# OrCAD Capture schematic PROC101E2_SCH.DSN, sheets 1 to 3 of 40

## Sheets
1 04. BLOCK DIAGRAM_XDS110: title: BLOCK DIAGRAM_XDS110; rev: E2
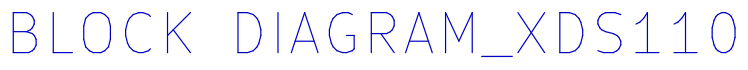
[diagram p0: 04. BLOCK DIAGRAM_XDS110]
2 16. CPSW RGMII_1 ETHERNET PHY: size C; title: CPSW RGMII_1 ETHERNET PHY
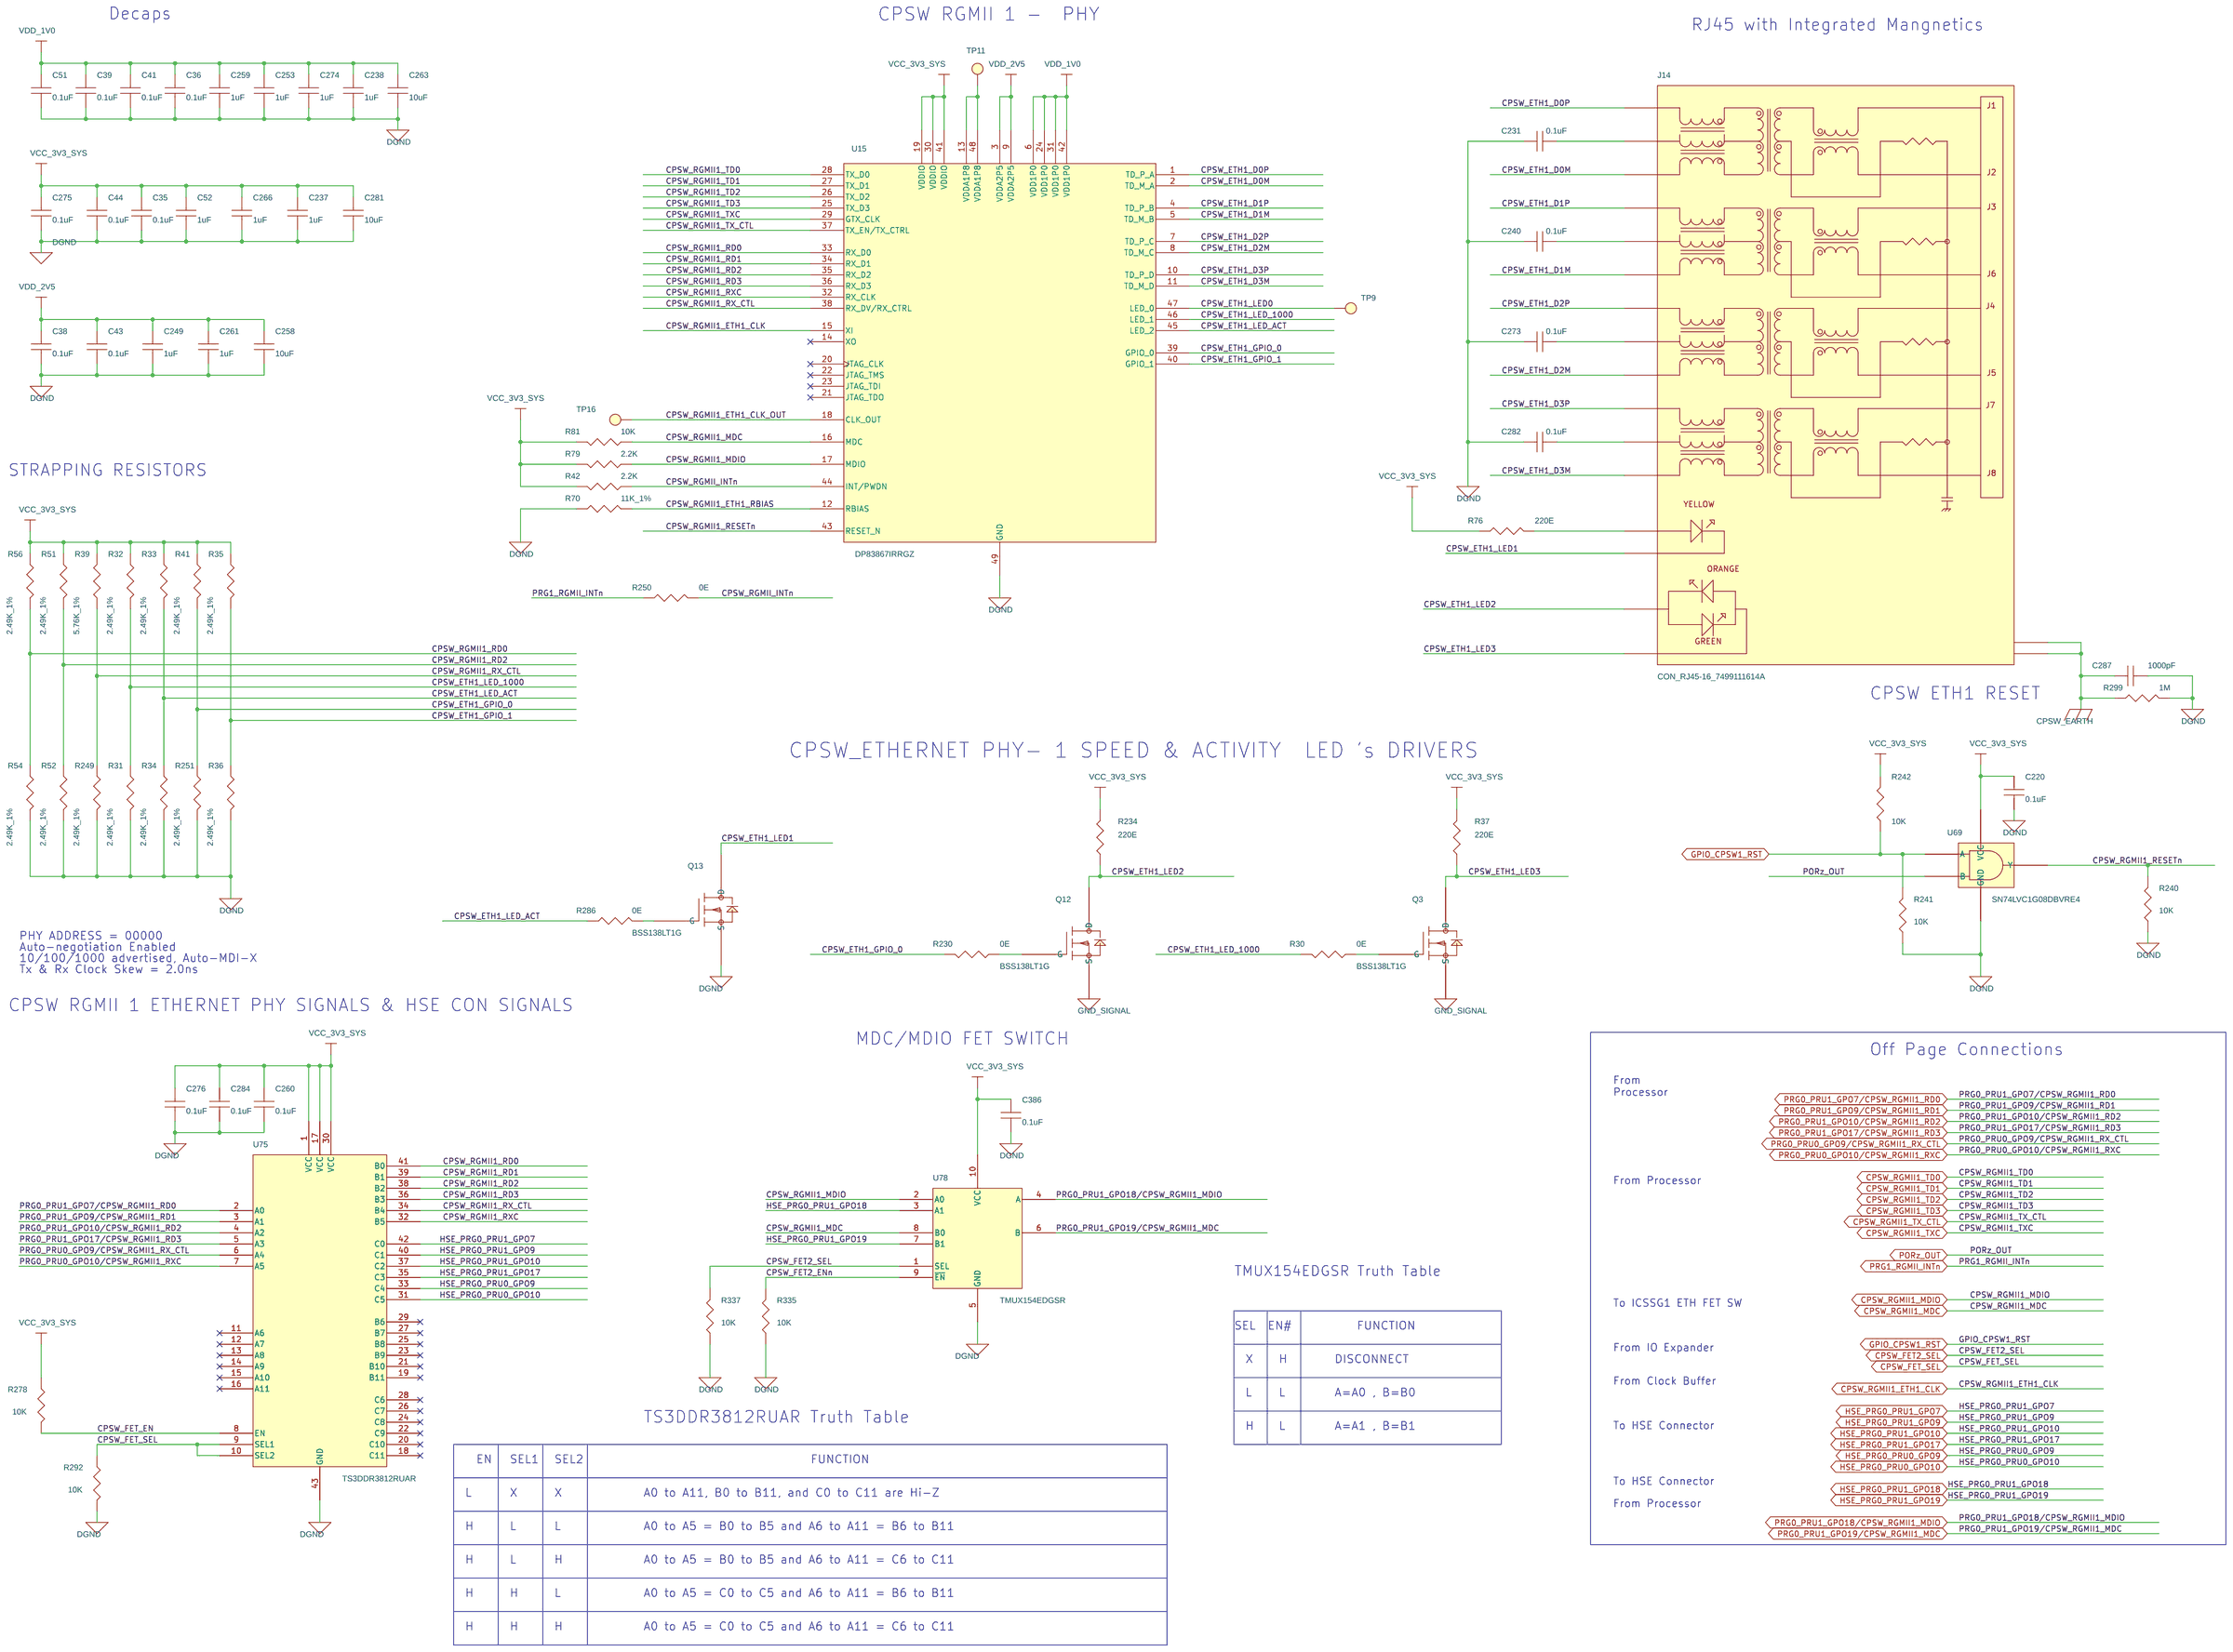
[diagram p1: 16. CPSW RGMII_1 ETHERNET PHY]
3 10.SOC POWER CAPS: size C; title: SOC POWER CAPS
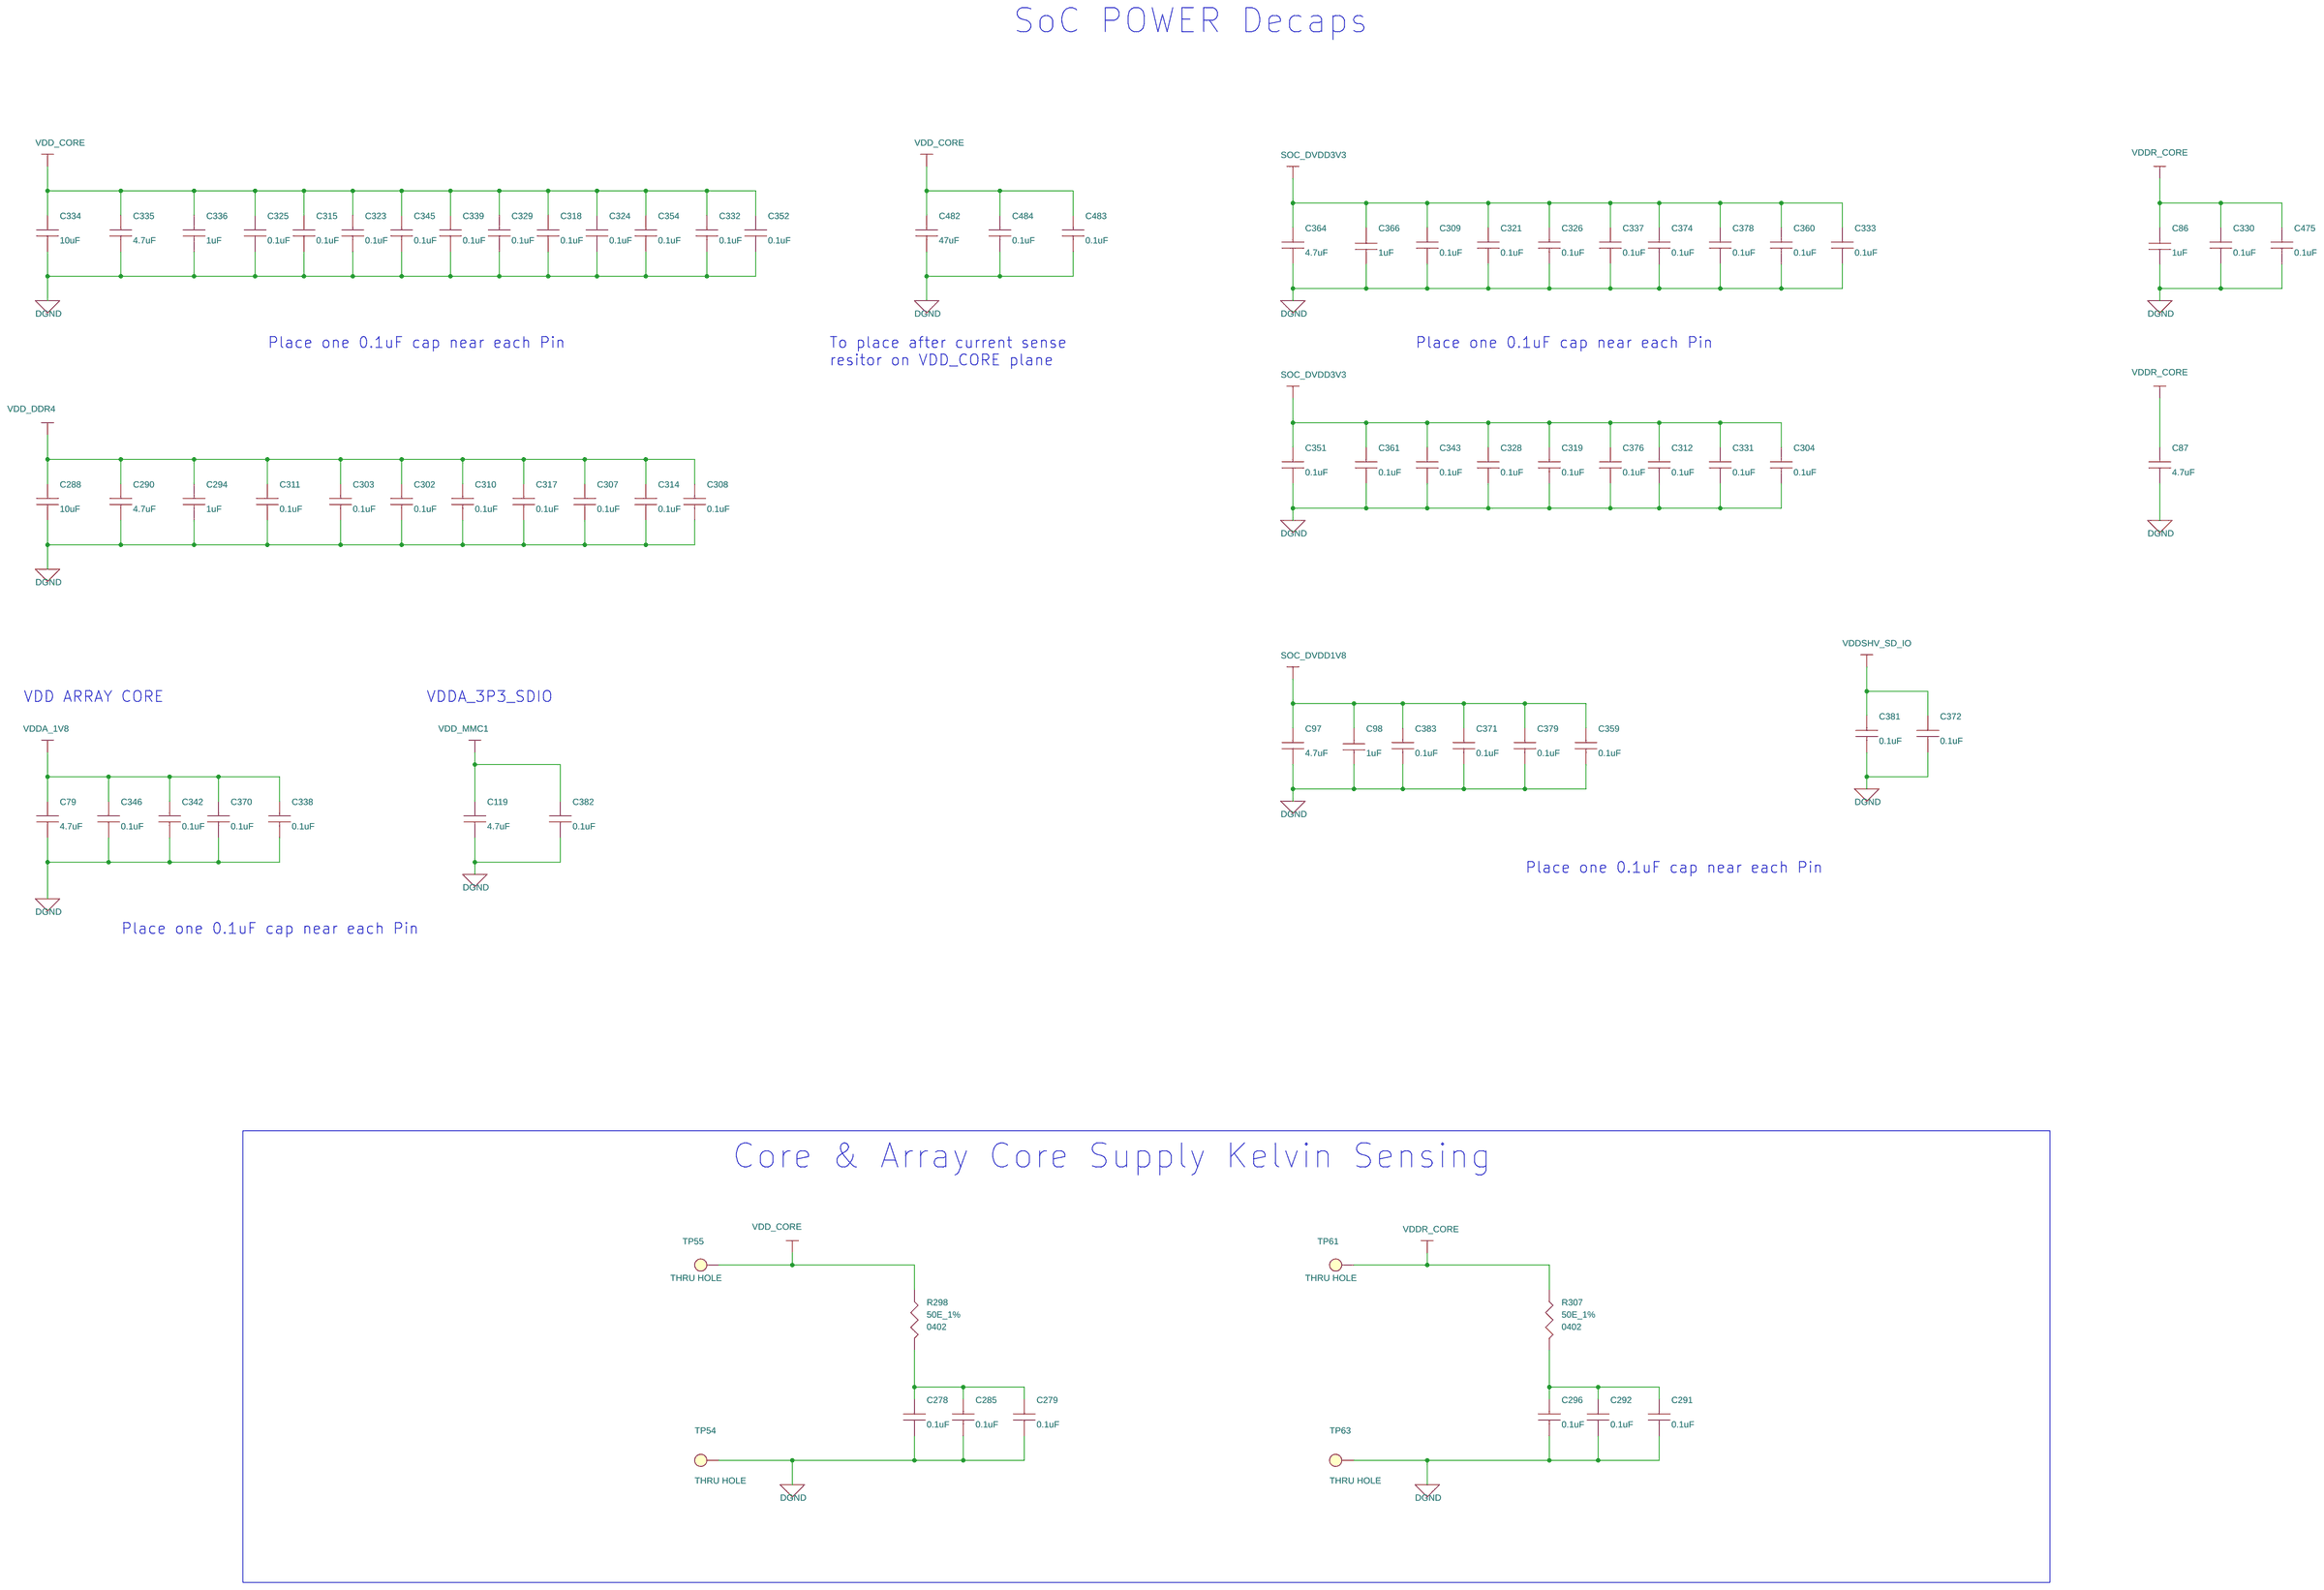
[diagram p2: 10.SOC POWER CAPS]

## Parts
sheet 10.SOC POWER CAPS
C79  4.7uF  [CAP0402_0-75]
C86  1uF  [CAP0402_0-75]
C87  4.7uF  [CAP0402_0-75]
C97  4.7uF  [CAP0402_0-75]
C98  1uF  [CAP0402_0-75]
C119  4.7uF  [CAP0402_0-75]
C278  0.1uF  [CAP0402_0-75]
C279  0.1uF  [CAP0402_0-75]
C285  0.1uF  [CAP0402_0-75]
C288  10uF  [CAP0402_0-75]
C290  4.7uF  [CAP0402_0-75]
C291  0.1uF  [CAP0402_0-75]
C292  0.1uF  [CAP0402_0-75]
C294  1uF  [CAP0402_0-75]
C296  0.1uF  [CAP0402_0-75]
C302  0.1uF  [CAP0201_0-5]
C303  0.1uF  [CAP0201_0-5]
C304  0.1uF  [CAP0201_0-5]
C307  0.1uF  [CAP0201_0-5]
C308  0.1uF  [CAP0201_0-5]
C309  0.1uF  [CAP0201_0-5]
C310  0.1uF  [CAP0201_0-5]
C311  0.1uF  [CAP0201_0-5]
C312  0.1uF  [CAP0201_0-5]
C314  0.1uF  [CAP0201_0-5]
C315  0.1uF  [CAP0201_0-5]
C317  0.1uF  [CAP0201_0-5]
C318  0.1uF  [CAP0201_0-5]
C319  0.1uF  [CAP0201_0-5]
C321  0.1uF  [CAP0201_0-5]
C323  0.1uF  [CAP0201_0-5]
C324  0.1uF  [CAP0201_0-5]
C325  0.1uF  [CAP0201_0-5]
C326  0.1uF  [CAP0201_0-5]
C328  0.1uF  [CAP0201_0-5]
C329  0.1uF  [CAP0201_0-5]
C330  0.1uF  [CAP0201_0-5]
C331  0.1uF  [CAP0201_0-5]
C332  0.1uF  [CAP0201_0-5]
C333  0.1uF  [CAP0201_0-5]
C334  10uF  [CAP0402_0-75]
C335  4.7uF  [CAP0402_0-75]
C336  1uF  [CAP0402_0-75]
C337  0.1uF  [CAP0201_0-5]
C338  0.1uF  [CAP0201_0-5]
C339  0.1uF  [CAP0201_0-5]
C342  0.1uF  [CAP0201_0-5]
C343  0.1uF  [CAP0201_0-5]
C345  0.1uF  [CAP0201_0-5]
C346  0.1uF  [CAP0201_0-5]
C351  0.1uF  [CAP0201_0-5]
C352  0.1uF  [CAP0201_0-5]
C354  0.1uF  [CAP0201_0-5]
C359  0.1uF  [CAP0201_0-5]
C360  0.1uF  [CAP0201_0-5]
C361  0.1uF  [CAP0201_0-5]
C364  4.7uF  [CAP0402_0-75]
C366  1uF  [CAP0402_0-75]
C370  0.1uF  [CAP0201_0-5]
C371  0.1uF  [CAP0201_0-5]
C372  0.1uF  [CAP0201_0-5]
C374  0.1uF  [CAP0201_0-5]
C376  0.1uF  [CAP0201_0-5]
C378  0.1uF  [CAP0201_0-5]
C379  0.1uF  [CAP0201_0-5]
C381  0.1uF  [CAP0201_0-5]
C382  0.1uF  [CAP0201_0-5]
C383  0.1uF  [CAP0201_0-5]
C475  0.1uF  [CAP0201_0-5]
C482  47uF  [CAP1206_2]
C483  0.1uF  [CAP0201_0-5]
C484  0.1uF  [CAP0201_0-5]
R298  50E_1%  [RES0402_0-75]
R307  50E_1%  [RES0402_0-75]
TP54  THRU HOLE  [TP_40X65]
TP55  THRU HOLE  [TP_40X65]
TP61  THRU HOLE  [TP_40X65]
TP63  THRU HOLE  [TP_40X65]
sheet 16. CPSW RGMII_1 ETHERNET PHY
C35  0.1uF  [CAP0402_0-75]
C36  0.1uF  [CAP0402_0-75]
C38  0.1uF  [CAP0402_0-75]
C39  0.1uF  [CAP0402_0-75]
C41  0.1uF  [CAP0402_0-75]
C43  0.1uF  [CAP0402_0-75]
C44  0.1uF  [CAP0402_0-75]
C51  0.1uF  [CAP0402_0-75]
C52  1uF  [CAP0402_0-75]
C220  0.1uF  [CAP0402_0-75]
C231  0.1uF  [CAP0201_0-5]
C237  1uF  [CAP0402_0-75]
C238  1uF  [CAP0402_0-75]
C240  0.1uF  [CAP0201_0-5]
C249  1uF  [CAP0402_0-75]
C253  1uF  [CAP0402_0-75]
C258  10uF  [CAP0402_0-75]
C259  1uF  [CAP0402_0-75]
C260  0.1uF  [CAP0402_0-75]
C261  1uF  [CAP0402_0-75]
C263  10uF  [CAP0402_0-75]
C266  1uF  [CAP0402_0-75]
C273  0.1uF  [CAP0201_0-5]
C274  1uF  [CAP0402_0-75]
C275  0.1uF  [CAP0402_0-75]
C276  0.1uF  [CAP0402_0-75]
C281  10uF  [CAP0402_0-75]
C282  0.1uF  [CAP0201_0-5]
C284  0.1uF  [CAP0402_0-75]
C287  1000pF  [CAP1206_1-75]
C386  0.1uF  [CAP0402_0-75]
J14  CON_RJ45-16_7499111614A  [CON_RJ45-16_7499111614A_S_R_T_15-8]
Q3  BSS138LT1G  [SOT23-123_1-2]
Q12  BSS138LT1G  [SOT23-123_1-2]
Q13  BSS138LT1G  [SOT23-123_1-2]
R30  0E  [RES0402_0-5]
R31  2.49K_1%  [RES0402_0-5]
R32  2.49K_1%  [RES0402_0-5]
R33  2.49K_1%  [RES0402_0-5]
R34  2.49K_1%  [RES0402_0-5]
R35  2.49K_1%  [RES0402_0-5]
R36  2.49K_1%  [RES0402_0-5]
R37  220E  [RES0402_0-5]
R39  5.76K_1%  [RES0402_0-5]
R41  2.49K_1%  [RES0402_0-5]
R42  2.2K  [RES0402_0-5]
R51  2.49K_1%  [RES0402_0-5]
R52  2.49K_1%  [RES0402_0-5]
R54  2.49K_1%  [RES0402_0-5]
R56  2.49K_1%  [RES0402_0-5]
R70  11K_1%  [RES0402_0-5]
R76  220E  [RES0402_0-5]
R79  2.2K  [RES0402_0-5]
R81  10K  [RES0402_0-5]
R230  0E  [RES0402_0-5]
R234  220E  [RES0402_0-5]
R240  10K  [RES0402_0-5]
R241  10K  [RES0402_0-5]
R242  10K  [RES0402_0-5]
R249  2.49K_1%  [RES0402_0-5]
R250  0E  [RES0402_0-5]
R251  2.49K_1%  [RES0402_0-5]
R278  10K  [RES0402_0-5]
R286  0E  [RES0402_0-5]
R292  10K  [RES0402_0-5]
R299  1M  [RES0603_0-75]
R335  10K  [RES0402_0-5]
R337  10K  [RES0402_0-5]
TP9  TP20_SMD  [TP20_SMD]
TP11  TP20_SMD  [TP20_SMD]
TP16  TP20_SMD  [TP20_SMD]
U15  DP83867IRRGZ  [QFN48_19-68_280X280_1]
U69  SN74LVC1G08DBVRE4  [SOT23-5]
U75  TS3DDR3812RUAR  [TQFN42_19-68_140X360_0-8]
U78  TMUX154EDGSR  [MSOP10_19-68_120X120_1-1]

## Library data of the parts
C79 C87 C97 C119 C290 C335 C364 = CAP: CAP CERAMIC 4.7uF 10V 20% X5R 0402; Chkd/date: MANIRAJA/230118; Crtd /date: MANIRAJA/230118; Custom_Duty: 15%; Customs_HS_Code: 85322990; Distributor_name: DIGIKEY; Distributor_part_number: 478-10791-1-ND; Footprint Path: Y:\MIS_DATABASE\Library\ALTIUM_TOOL\PCB_FOOTPRINTS\Altium_Footprint_Lib.PcbLib; Height: 0.71MM; Library Path: Y:\MIS_DATABASE\Library\ALTIUM_TOOL\SCHEMATICS_PARTS\MS_DISCRETE_Library.schlib; Mfr_name: AVX CORPORATION; Mfr_part_number: 0402ZD475MAT2A; Mistral Part No: 120012060002-R; Package: 0402; Part_type: CAPACITORS\CERAMIC; Project: TI_MAXIE_CPB; RoHS: RoHS; Temperature: -55°C+85°C; Tolerance: 20%; Voltage: 10V; Wattage: NA; Weight: 0.65mg; Datasheet: Y:\MIS_DATABASE\DATASHEETS\CAPACITORS\AVX_MLC.PDF
C52 C86 C98 C237 C238 C249 C253 C259 C261 C266 C274 C294 C336 C366 = CAP: CAP CERAMIC 1uF 10V 20% X5R 0402; Chkd/date: MANIRAJA/210820; Crtd /date: ALVY/190820; Custom_Duty: 15%; Customs_HS_Code: 85322990; Distributor_name: DIGIKEY; Distributor_part_number: 732-7489-1-ND; Footprint Path: Y:\MIS_DATABASE\Library\ALTIUM_TOOL\PCB_FOOTPRINTS\Altium_Footprint_Lib.PcbLib; Height: 0.55MM; Library Path: Y:\MIS_DATABASE\Library\ALTIUM_TOOL\SCHEMATICS_PARTS\MS_DISCRETE_Library.schlib; Mfr_name: WURTH ELECTRONICS; Mfr_part_number: 885012105012; Mistral Part No: 120020080009-R; Package: 0402; Part_type: CAPACITORS\CERAMIC; Project: AM64x_EVM_BRD; RoHS: RoHS; Temperature: -55°C+85°C; Tolerance: 20%; Voltage: 10V; Wattage: NA; Weight: 0.65mg; Datasheet: Y:\MIS_DATABASE\DATASHEETS\CAPACITORS\885012105012.PDF
C35 C36 C38 C39 C41 C43 C44 C51 C220 C260 C275 C276 C278 C279 C284 C285 C291 C292 C296 C386 = CAP: CAP CERAMIC 0.1uF 25V 20% X5R 0402; Alt_Mfr_name: YAGEO AMERICA; Alt_Mfr_part_number: CC0402KRX5R8BB104; Chkd/date: MANIRAJA/170820; Crtd /date: ALVY/170820; Custom_Duty: 15%; Customs_HS_Code: 85322990; Distributor_name: DIGIKEY; Distributor_part_number: 732-7495-1-ND; Footprint Path: Y:\MIS_DATABASE\Library\ALTIUM_TOOL\PCB_FOOTPRINTS\Altium_Footprint_Lib.PcbLib; Height: 0.55MM; Library Path: Y:\MIS_DATABASE\Library\ALTIUM_TOOL\SCHEMATICS_PARTS\MS_DISCRETE_Library.schlib; Mfr_name: WURTH ELECTRONICS; Mfr_part_number: 885012105018; Mistral Part No: 120020080003-R; Package: 0402; Part_type: CAPACITORS\CERAMIC; Project: AM64x_EVM_BRD; RoHS: RoHS; Temperature: -55°C+85°C; Tolerance: 20%; Voltage: 25V; Wattage: NA; Weight: 0.65mg; Datasheet: Y:\MIS_DATABASE\DATASHEETS\CAPACITORS\885012105018.PDF
C258 C263 C281 C288 C334 = CAP: CAP CERAMIC 10uF 10V 20% X5R 0402; Chkd/date: MANIRAJA/300520; Crtd /date: ALVY/260520; Custom_Duty: 15%; Customs_HS_Code: 85322990; Distributor_name: DIGIKEY; Distributor_part_number: 490-GRM155R61A106ME11DTR-ND; Footprint Path: Y:\MIS_DATABASE\Library\ALTIUM_TOOL\PCB_FOOTPRINTS\Altium_Footprint_Lib.PcbLib; Height: 0.55MM; Library Path: Y:\MIS_DATABASE\Library\ALTIUM_TOOL\SCHEMATICS_PARTS\MS_DISCRETE_Library.schlib; Mfr_name: MURATA; Mfr_part_number: GRM155R61A106ME11D; Mistral Part No: 120013110019-R; Package: 0402; Part_type: CAPACITORS\CERAMIC; Project: QCS610_NANOSOM; RoHS: RoHS; Temperature: -55°C+85°C; Tolerance: 20%; Voltage: 10V; Wattage: NA; Weight: 3.1mg; Datasheet: Y:\MIS_DATABASE\DATASHEETS\CAPACITORS\MURATA-GXX-SER_NOV17.PDF
C231 C240 C273 C282 C302-C304 C307-C312 C314 C315 C317-C319 C321 C323-C326 C328-C333 C337-C339 C342 C343 C345 C346 C351 C352 C354 C359-C361 C370-C372 C374 C376 C378 C379 C381-C383 C475 C483 C484 = CAP: CAP CERAMIC 0.1uF 16V 10% X5R 0201; Chkd/date: MANIRAJA/120218; Crtd /date: MANIRAJA/120218; Custom_Duty: 15%; Customs_HS_Code: 85322990; Distributor_name: DIGIKEY; Distributor_part_number: 490-16742-1-ND; Footprint Path: Y:\MIS_DATABASE\Library\ALTIUM_TOOL\PCB_FOOTPRINTS\Altium_Footprint_Lib.PcbLib; Height: 0.33MM; Library Path: Y:\MIS_DATABASE\Library\ALTIUM_TOOL\SCHEMATICS_PARTS\MS_DISCRETE_Library.schlib; Mfr_name: MURATA; Mfr_part_number: GRM033R61C104KE84J; Mistral Part No: 120009030072-R; Package: 0201; Part_type: CAPACITORS\CERAMIC; Project: TI_MAXIE_CPB; RoHS: RoHS; Temperature: -55°C+85°C; Tolerance: 10%; Voltage: 16V; Wattage: NA; Weight: 0.33mg; Datasheet: Y:\MIS_DATABASE\DATASHEETS\CAPACITORS\GRM033R61C104KE84.PDF
C482 = CAP: CAP CERAMIC 47uF 25V 20% X5R 1206; Chkd/date: MANIRAJA/230118; Crtd /date: MANIRAJA/230118; Custom_Duty: 15%; Customs_HS_Code: 85322990; Distributor_name: DIGIKEY; Distributor_part_number: 490-16268-1-ND; Footprint Path: Y:\MIS_DATABASE\Library\ALTIUM_TOOL\PCB_FOOTPRINTS\Altium_Footprint_Lib.PcbLib; Height: 1.80MM; Library Path: Y:\MIS_DATABASE\Library\ALTIUM_TOOL\SCHEMATICS_PARTS\MS_DISCRETE_Library.schlib; Mfr_name: MURATA; Mfr_part_number: GRM31CR61E476ME44L; Mistral Part No: 120013050002-R; Package: 1206; Part_type: CAPACITORS\CERAMIC; Project: TI_MAXIE_CPB; RoHS: RoHS; Temperature: -55°C+85°C; Tolerance: 20%; Voltage: 25V; Wattage: NA; Weight: 40mg; Datasheet: Y:\MIS_DATABASE\DATASHEETS\CAPACITORS\MURATA-GXX-SER_NOV17.PDF
R298 R307 = RESISTOR: RES 50E 1/8W 1% 0402; Chkd/date: MANIRAJA/160218; Crtd /date: ALVY/140218; Custom_Duty: 15%; Customs_HS_Code: 85332119; Distributor_name: DIGIKEY; Distributor_part_number: 1284-1326-1-ND; Footprint Path: Y:\MIS_DATABASE\Library\ALTIUM_TOOL\PCB_FOOTPRINTS\Altium_Footprint_Lib.PcbLib; Height: 0.60MM; Library Path: Y:\MIS_DATABASE\Library\ALTIUM_TOOL\SCHEMATICS_PARTS\MS_DISCRETE_Library.schlib; Mfr_name: ATC; Mfr_part_number: 504L50R0FTNCFT; Mistral Part No: 110018020017-R; Package: 0402; Part_type: RESISTORS\FIXED; Project: TI_SVB_MAXWELL_SPM; RoHS: RoHS; Temperature: -40°C+125°C; Tolerance: 1%; Voltage: NA; Wattage: 1/8W; Weight: 0.65mg; Datasheet: Y:\MIS_DATABASE\DATASHEETS\RESISTORS\ATC504L-SERIES.PDF
TP54 TP55 TP61 TP63 = TESTPOINT: TESTPOINT 1.0MM DRILL PTH; Chkd/date: MAZHAR/271211; Crtd /date: SHREESHAIL/041005; Distributor_name: NA; Distributor_part_number: NA; Height: NA; Mfr_name: LOCAL; Mistral Part No: 130009030938; Package: THRU-HOLE; Project: HSE; Datasheet: NA
C287 = CAP: CAP CERAMIC 1000pF 2KV 10% X7R 1206; Chkd/date: SHREESHAIL/291106; Crtd /date: MAZHAR/281106; Custom_Duty: 15%; Customs_HS_Code: 85322990; Distributor_name: DIGIKEY; Distributor_part_number: 478-2956-1-ND; Footprint Path: Y:\MIS_DATABASE\Library\ALTIUM_TOOL\PCB_FOOTPRINTS\Altium_Footprint_Lib.PcbLib; Height: 1.52MM; Library Path: Y:\MIS_DATABASE\Library\ALTIUM_TOOL\SCHEMATICS_PARTS\MS_DISCRETE_Library.schlib; Mfr_name: AVX CORPORATION; Mfr_part_number: 1206GC102KAT1A; Mistral Part No: 120015080006-R; Package: 1206; Part_type: CAPACITORS\CERAMIC; Project: ADR1B; RoHS: RoHS; Temperature: -55°C+125°C; Tolerance: 10%; Voltage: 2KV; Wattage: NA; Weight: 16.2mg; Datasheet: Y:\MIS_DATABASE\DATASHEETS\CAPACITORS\AVX_HV-MLC.PDF
J14 = CON_RJ45-16_7499111614A: CON JACK RJ-45 16POS FEMALE RT TH; Chkd/date: MANIRAJA/060519; Crtd /date: ALVY/060519; Custom_Duty: 24%; Customs_HS_Code: 85369090; Distributor_name: DIGIKEY; Distributor_part_number: 732-12036-5-ND; Footprint Path: Y:\MIS_DATABASE\Library\ALTIUM_TOOL\PCB_FOOTPRINTS\Altium_Footprint_Lib.PcbLib; Height: 15.79MM; Library Path: Y:\MIS_DATABASE\Library\ALTIUM_TOOL\SCHEMATICS_PARTS\MS_CONNECTOR_Library.schlib; Mfr_name: WURTH ELECTRONICS; Mfr_part_number: 7499111614A; Mistral Part No: 150019050003-R; Package: THRU-HOLE; Part_type: CONNECTOR\JACK; Project: J7ES_ENET_DP83869HM_EXP; RoHS: RoHS; Temperature: 0°C+70°C; Tolerance: NA; Voltage: NA; Wattage: NA; Weight: 9360mg; Datasheet: Y:\MIS_DATABASE\DATASHEETS\CONNECTORS\7499111614A.PDF
Q3 Q12 Q13 = MOSFET_BSS138LT1G: IC MOSFET N-CHANNEL 50V 200mA SOT23-3; Chkd/date: MANIRAJA/250219; Crtd /date: JEBRAN/060416; Custom_Duty: 15%; Customs_HS_Code: 85423100; Distributor_name: DIGIKEY; Distributor_part_number: BSS138LT1GOSCT-ND; Footprint Path: Y:\MIS_DATABASE\Library\ALTIUM_TOOL\PCB_FOOTPRINTS\Altium_Footprint_Lib.PcbLib; Height: 1.11MM; Library Path: Y:\MIS_DATABASE\Library\ALTIUM_TOOL\SCHEMATICS_PARTS\MS_MOSFET_Library.schlib; Library Ref: MOSFET_BSS138W; Mfr_name: ON SEMICONDUCTOR; Mistral Part No: 142016040001-R; Package: SOT23-3; Part_type: ICS\POWER\MOSFET; Project: LRDE_ABCM; RoHS: RoHS; Temperature: -55°C+150°C; Tolerance: NA; Voltage: NA; Wattage: NA; Weight: 8mg; Datasheet: Y:\MIS_DATABASE\DATASHEETS\DISCRETES\TRANSISTORS_FETS\BSS138LT1G.PDF
R30 R230 R250 R286 = RESISTOR: RES 0E 1/16W JUMPER 0402; Chkd/date: VASANTHA/201216; Crtd /date: MUDDU/190810; Custom_Duty: 15%; Customs_HS_Code: 85332119; Distributor_name: DIGIKEY; Distributor_part_number: 541-0.0JCT-ND; Footprint Path: Y:\MIS_DATABASE\Library\ALTIUM_TOOL\PCB_FOOTPRINTS\Altium_Footprint_Lib.PcbLib; Height: 0.40MM; Library Path: Y:\MIS_DATABASE\Library\ALTIUM_TOOL\SCHEMATICS_PARTS\MS_DISCRETE_Library.schlib; Mfr_name: VISHAY; Mfr_part_number: CRCW04020000Z0ED; Mistral Part No: 110010080019-R; Package: 0402; Part_type: RESISTORS\FIXED; Project: PB_BUGBASE; RoHS: RoHS; Temperature: -55°C+155°C; Tolerance: NA; Voltage: NA; Wattage: 1/16W; Weight: 0.65mg; Datasheet: Y:\MIS_DATABASE\DATASHEETS\RESISTORS\CRCW0603.PDF
R31-R36 R41 R51 R52 R54 R56 R251 = RESISTOR: RES 2.49K 1/16W 1% 0402; Assembly: DNI; Chkd/date: VASANTHA/270516; Crtd /date: VASANTHA/270516; Custom_Duty: 15%; Customs_HS_Code: 85332119; Distributor_name: DIGIKEY; Distributor_part_number: 311-2.49KLRCT-ND; Footprint Path: Y:\MIS_DATABASE\Library\ALTIUM_TOOL\PCB_FOOTPRINTS\Altium_Footprint_Lib.PcbLib; Height: 0.40MM; Library Path: Y:\MIS_DATABASE\Library\ALTIUM_TOOL\SCHEMATICS_PARTS\MS_DISCRETE_Library.schlib; Mfr_name: YAGEO AMERICA; Mfr_part_number: RC0402FR-072K49L; Mistral Part No: 110016050020-R; Package: 0402; Part_type: RESISTORS\FIXED; Project: TMDXCSKCC; RoHS: RoHS; Temperature: -55°C+155°C; Tolerance: 1%; Voltage: NA; Wattage: 1/16W; Weight: 0.65mg; Datasheet: Y:\MIS_DATABASE\DATASHEETS\RESISTORS\RCXXXXL-SER_MAR18.PDF
R37 R76 R234 = RESISTOR: RES 220E 1/10W 5% 0402; Chkd/date: VASANTHA/291216; Crtd /date: GEETHA/260406; Custom_Duty: 15%; Customs_HS_Code: 85332119; Distributor_name: DIGIKEY; Distributor_part_number: P220JCT-ND; Footprint Path: Y:\MIS_DATABASE\Library\ALTIUM_TOOL\PCB_FOOTPRINTS\Altium_Footprint_Lib.PcbLib; Height: 0.40MM; Library Path: Y:\MIS_DATABASE\Library\ALTIUM_TOOL\SCHEMATICS_PARTS\MS_DISCRETE_Library.schlib; Mfr_name: PANASONIC-ECG; Mfr_part_number: ERJ-2GEJ221X; Mistral Part No: 110009030506-R; Package: 0402; Part_type: RESISTORS\FIXED; Project: RED EYE; RoHS: RoHS; Temperature: -55°C+155°C; Tolerance: 5%; Voltage: NA; Wattage: 1/10W; Weight: 0.8mg; Datasheet: Y:\MIS_DATABASE\DATASHEETS\RESISTORS\PAN-ERJSER_NOV17.PDF
R39 = RESISTOR: RES 5.76K 1/10W 1% 0402; Chkd/date: MAZHAR/150709; Crtd /date: USMAN/220808; Custom_Duty: 15%; Customs_HS_Code: 85332119; Distributor_name: DIGIKEY; Distributor_part_number: P5.76KLCT-ND; Footprint Path: Y:\MIS_DATABASE\Library\ALTIUM_TOOL\PCB_FOOTPRINTS\Altium_Footprint_Lib.PcbLib; Height: 0.40MM; Library Path: Y:\MIS_DATABASE\Library\ALTIUM_TOOL\SCHEMATICS_PARTS\MS_DISCRETE_Library.schlib; Mfr_name: PANASONIC-ECG; Mfr_part_number: ERJ-2RKF5761X; Mistral Part No: 110009030945-R; Package: 0402; Part_type: RESISTORS\FIXED; Project: CPB; RoHS: RoHS; Temperature: -55°C+155°C; Tolerance: 1%; Voltage: NA; Wattage: 1/10W; Weight: 0.8mg; Datasheet: Y:\MIS_DATABASE\DATASHEETS\RESISTORS\PAN-ERJSER_NOV17.PDF
R42 R79 = RESISTOR: RES 2.2K 1/16W 5% 0402; Chkd/date: VASANTHA/061216; Crtd /date: BAVISH/021210; Custom_Duty: 15%; Customs_HS_Code: 85332119; Distributor_name: DIGIKEY; Distributor_part_number: 311-2.2KJRCT-ND; Footprint Path: Y:\MIS_DATABASE\Library\ALTIUM_TOOL\PCB_FOOTPRINTS\Altium_Footprint_Lib.PcbLib; Height: 0.40MM; Library Path: Y:\MIS_DATABASE\Library\ALTIUM_TOOL\SCHEMATICS_PARTS\MS_DISCRETE_Library.schlib; Mfr_name: YAGEO AMERICA; Mfr_part_number: RC0402JR-072K2L; Mistral Part No: 110010120018-R; Package: 0402; Part_type: RESISTORS\FIXED; Project: TE4; RoHS: RoHS; Temperature: -55°C+155°C; Tolerance: 5%; Voltage: NA; Wattage: 1/16W; Weight: 0.65mg; Datasheet: Y:\MIS_DATABASE\DATASHEETS\RESISTORS\RCXXXXL-SER_MAR18.PDF
R70 = RESISTOR: RES 11K 1/16W 1% 0402; Chkd/date: VASANTHA/251115; Crtd /date: VASANTHA/251115; Custom_Duty: 15%; Customs_HS_Code: 85332119; Distributor_name: DIGIKEY; Distributor_part_number: 311-11.0KLRCT-ND; Footprint Path: Y:\MIS_DATABASE\Library\ALTIUM_TOOL\PCB_FOOTPRINTS\Altium_Footprint_Lib.PcbLib; Height: 0.40MM; Library Path: Y:\MIS_DATABASE\Library\ALTIUM_TOOL\SCHEMATICS_PARTS\MS_DISCRETE_Library.schlib; Mfr_name: YAGEO AMERICA; Mfr_part_number: RC0402FR-0711KL; Mistral Part No: 110015110012-R; Package: 0402; Part_type: RESISTORS\FIXED; Project: TI_VLAN_SWITCH; RoHS: RoHS; Temperature: -55°C+155°C; Tolerance: 1%; Voltage: NA; Wattage: 1/16W; Weight: 0.65mg; Datasheet: Y:\MIS_DATABASE\DATASHEETS\RESISTORS\RCXXXXL-SER_MAR18.PDF
R81 R240 R241 = RESISTOR: RES 10K 1/16W 5% 0402; Assembly: DNI; Chkd/date: VASANTHA/061216; Crtd /date: MAZHAR/230805; Custom_Duty: 15%; Customs_HS_Code: 85332119; Distributor_name: DIGIKEY; Distributor_part_number: 311-10KJRCT-ND; Footprint Path: Y:\MIS_DATABASE\Library\ALTIUM_TOOL\PCB_FOOTPRINTS\Altium_Footprint_Lib.PcbLib; Height: 0.40MM; Library Path: Y:\MIS_DATABASE\Library\ALTIUM_TOOL\SCHEMATICS_PARTS\MS_DISCRETE_Library.schlib; Mfr_name: YAGEO AMERICA; Mfr_part_number: RC0402JR-0710KL; Mistral Part No: 110011060021-R; Package: 0402; Part_type: RESISTORS\FIXED; Project: HSE; RoHS: RoHS; Temperature: -55°C+155°C; Tolerance: 5%; Voltage: NA; Wattage: 1/16W; Weight: 0.65mg; Datasheet: Y:\MIS_DATABASE\DATASHEETS\RESISTORS\RCXXXXL-SER_MAR18.PDF
R242 R278 R292 R335 R337 = RESISTOR: RES 10K 1/16W 5% 0402; Chkd/date: VASANTHA/061216; Crtd /date: MAZHAR/230805; Custom_Duty: 15%; Customs_HS_Code: 85332119; Distributor_name: DIGIKEY; Distributor_part_number: 311-10KJRCT-ND; Footprint Path: Y:\MIS_DATABASE\Library\ALTIUM_TOOL\PCB_FOOTPRINTS\Altium_Footprint_Lib.PcbLib; Height: 0.40MM; Library Path: Y:\MIS_DATABASE\Library\ALTIUM_TOOL\SCHEMATICS_PARTS\MS_DISCRETE_Library.schlib; Mfr_name: YAGEO AMERICA; Mfr_part_number: RC0402JR-0710KL; Mistral Part No: 110011060021-R; Package: 0402; Part_type: RESISTORS\FIXED; Project: HSE; RoHS: RoHS; Temperature: -55°C+155°C; Tolerance: 5%; Voltage: NA; Wattage: 1/16W; Weight: 0.65mg; Datasheet: Y:\MIS_DATABASE\DATASHEETS\RESISTORS\RCXXXXL-SER_MAR18.PDF
R249 = RESISTOR: RES 2.49K 1/16W 1% 0402; Chkd/date: VASANTHA/270516; Crtd /date: VASANTHA/270516; Custom_Duty: 15%; Customs_HS_Code: 85332119; Distributor_name: DIGIKEY; Distributor_part_number: 311-2.49KLRCT-ND; Footprint Path: Y:\MIS_DATABASE\Library\ALTIUM_TOOL\PCB_FOOTPRINTS\Altium_Footprint_Lib.PcbLib; Height: 0.40MM; Library Path: Y:\MIS_DATABASE\Library\ALTIUM_TOOL\SCHEMATICS_PARTS\MS_DISCRETE_Library.schlib; Mfr_name: YAGEO AMERICA; Mfr_part_number: RC0402FR-072K49L; Mistral Part No: 110016050020-R; Package: 0402; Part_type: RESISTORS\FIXED; Project: TMDXCSKCC; RoHS: RoHS; Temperature: -55°C+155°C; Tolerance: 1%; Voltage: NA; Wattage: 1/16W; Weight: 0.65mg; Datasheet: Y:\MIS_DATABASE\DATASHEETS\RESISTORS\RCXXXXL-SER_MAR18.PDF
R299 = RESISTOR: RES 1M 1/10W 5% 0603; Chkd/date: VASANTHA/060217; Crtd /date: USMAN/111207; Custom_Duty: 15%; Customs_HS_Code: 85332119; Distributor_name: DIGIKEY; Distributor_part_number: P1.0MGCT-ND; Footprint Path: Y:\MIS_DATABASE\Library\ALTIUM_TOOL\PCB_FOOTPRINTS\Altium_Footprint_Lib.PcbLib; Height: 0.55MM; Library Path: Y:\MIS_DATABASE\Library\ALTIUM_TOOL\SCHEMATICS_PARTS\MS_DISCRETE_Library.schlib; Mfr_name: PANASONIC-ECG; Mfr_part_number: ERJ-3GEYJ105V; Mistral Part No: 110009030413-R; Package: 0603; Part_type: RESISTORS\FIXED; Project: BSN; RoHS: RoHS; Temperature: -55°C+155°C; Tolerance: 5%; Voltage: NA; Wattage: 1/10W; Weight: 2mg; Datasheet: Y:\MIS_DATABASE\DATASHEETS\RESISTORS\PAN-ERJSER_NOV17.PDF
TP9 TP11 TP16 = TESTPOINT: TESTPOINT CIR 20 SMD; Chkd/date: SHREESHAIL/171006; Crtd /date: MAZHAR/171006; Custom_Duty: NA; Customs_HS_Code: NA; Distributor_name: NA; Distributor_part_number: NA; Footprint Path: Y:\MIS_DATABASE\Library\ALTIUM_TOOL\PCB_FOOTPRINTS\Altium_Footprint_Lib.PcbLib; Height: NA; Library Path: Y:\MIS_DATABASE\Library\ALTIUM_TOOL\SCHEMATICS_PARTS\MS_DISCRETE_Library.schlib; MECHANICAL 3D STEP FILE: NA; Mfr_name: LOCAL; Mistral Part No: NA; Package: SMD; Project: BT MODULE_CSRBC04; RoHS: NA; Temperature: NA; Tolerance: NA; Voltage: NA; Wattage: NA; Weight: NA; Datasheet: NA
U15 = DP83867IRRGZ_VQFN48: IC HIGH IMMUNITY 10/100/1000 Mb/s ETHERNET PHY LAYER TRANSCEIVER VQFN48; Chkd/date: MANIRAJA/110817; Crtd /date: MANIRAJA/110817; Custom_Duty: 15%; Customs_HS_Code: 85423100; Distributor_name: DIGIKEY; Distributor_part_number: DP83867IRRGZT-ND; Height: 1.00MM; Mfr_name: TEXAS INSTRUMENTS; Mistral Part No: 143017080002-R; Package: VQFN48; Part_type: ICS\TELECOM\TRANSCEIVER; Project: TI_SVB_CONTROLLER CARD; RoHS: RoHS; Temperature: -40°C+85°C; Tolerance: NA; Voltage: NA; Wattage: NA; Weight: NA; Datasheet: Y:\MIS_DATABASE\DATASHEETS\ICS\DIGITAL\BUSTRANSCEIVER\DP83867I.PDF
U69 = SN74LVC1G08DBVRE4_SOT23-5: IC SINGLE 2-INPUT POSITIVE AND GATE SOT23-5; Chkd/date: SUHAS/221010; Crtd /date: USMAN/151008; Custom_Duty: 15%; Customs_HS_Code: 85423100; Distributor_name: DIGIKEY; Distributor_part_number: SN74LVC1G08DBVRE4-ND; Height: 1.45MM; Mfr_name: TEXAS INSTRUMENTS; Mistral Part No: 141009060026-R; Part_type: ICS\DIGITAL\GATES; Project: KHAN_MAIN; RoHS: Sb/ Br FREE; Temperature: -40°C+85°C; Datasheet: Y:\MIS_DATABASE\DATASHEETS\ICS\DIGITAL\GATES\SN74LVC1G08.PDF
U75 = TS3DDR3812RUAR_WQFN42: IC 12-CH 1:2 MUX/DEMUX SWITCH FOR DDR3 APPLICATION WQFN42; Chkd/date: MANIRAJA/250918; Crtd /date: ALVY/250918; Custom_Duty: 15%; Customs_HS_Code: 85423100; Distributor_name: DIGIKEY; Distributor_part_number: 296-28307-1-ND; Footprint Path: Y:\MIS_DATABASE\Library\ALTIUM_TOOL\PCB_FOOTPRINTS\Altium_Footprint_Lib.PcbLib; Height: 0.80MM; Library Path: Y:\MIS_DATABASE\Library\ALTIUM_TOOL\SCHEMATICS_PARTS\MS_COMBINATIONAL_Library.schlib; Mfr_name: TEXAS INSTRUMENTS; Mistral Part No: 141018090023-R; Package: WQFN42; Part_type: ICS\DIGITAL\COMBINATIONAL; Project: TI_J7ES_EVM_CP; RoHS: RoHS; Temperature: -40°C+85°C; Tolerance: NA; Voltage: NA; Wattage: NA; Weight: 54.8mg; Datasheet: Y:\MIS_DATABASE\DATASHEETS\ICS\DIGITAL\COMBINATIONAL\TS3DDR3812.PDF
U78 = TMUX154EDGSR_VSSOP10: IC ESD PROTECTED 2-CH 2:1 SWITCH WITH POWERED-OFF PROTECTION VSSOP10; Chkd/date: MANIRAJA/040918; Crtd /date: MANIRAJA/040918; Custom_Duty: 15%; Customs_HS_Code: 85423100; Distributor_name: DIGIKEY; Distributor_part_number: 296-48347-1-ND; Footprint Path: Y:\MIS_DATABASE\Library\ALTIUM_TOOL\PCB_FOOTPRINTS\Altium_Footprint_Lib.PcbLib; Height: 1.10MM; Library Path: Y:\MIS_DATABASE\Library\ALTIUM_TOOL\SCHEMATICS_PARTS\MS_ANALOG-APPLICATION_Library.schlib; Mfr_name: TEXAS INSTRUMENTS; Mistral Part No: 140118090001-R; Package: VSSOP10; Part_type: ICS\ANALOG\SWITCH; Project: DLRL_DFP_ATRUC CARD; RoHS: RoHS; Temperature: -40°C+85°C; Tolerance: NA; Voltage: NA; Wattage: NA; Weight: NA; Datasheet: Y:\MIS_DATABASE\DATASHEETS\ICS\ANALOG\TMUX154EXXX.PDF

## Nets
DGND: C35.2 C36.2 C38.2 C39.2 C41.2 C43.2 C44.2 C51.2 C52.2 C79.2 C86.1 C87.2 C97.2 C98.1 C119.2 C220.2 C231.1 C237.2 C238.2 C240.1 C249.2 C253.2 C258.2 C259.2 C260.2 C261.2 C263.2 C266.2 C273.1 C274.2 C275.2 C276.2 C278.2 C279.2 C281.2 C282.1 C284.2 C285.2 C287.2 C288.2 C290.2 C291.2 C292.2 C294.2 C296.2 C302.2 C303.2 C304.2 C307.2 C308.2 C309.2 C310.2 C311.2 C312.2 C314.2 C315.2 C317.2 C318.2 C319.2 C321.2 C323.2 C324.2 C325.2 C326.2 C328.2 C329.2 C330.2 C331.2 C332.2 C333.2 C334.2 C335.2 C336.2 C337.2 C338.2 C339.2 C342.2 C343.2 C345.2 C346.2 C351.2 C352.2 C354.2 C359.2 C360.2 C361.2 C364.2 C366.1 C370.2 C371.2 C372.2 C374.2 C376.2 C378.2 C379.2 C381.2 C382.2 C383.2 C386.2 C475.2 C482.2 C483.2 C484.2 Q3.2(S) Q12.2(S) Q13.2(S) R31.2 R34.2 R36.2 R52.2 R54.2 R70.2 R240.2 R241.2 R249.2 R251.2 R292.2 R299.2 R335.2 R337.2 TP54.1(TP) TP63.1(TP) U15.49(GND) U69.3(GND) U75.43(GND) U78.5(GND) ; also on sheet 4 5 6 7 8 9 10 11 12 13 14 15 16 17 18 19 20 21 22 23 24 25 26 27 28 29 30 39 40
VCC_3V3_SYS: C35.1 C44.1 C52.1 C220.1 C237.1 C260.1 C266.1 C275.1 C276.1 C281.1 C284.1 C386.1 R32.1 R33.1 R35.1 R37.2 R39.2 R41.1 R42.2 R51.1 R56.1 R76.1 R79.2 R81.1 R234.2 R242.2 R278.1 U15.19(VDDIO) U15.30(VDDIO) U15.41(VDDIO) U69.5(VCC) U75.1(VCC) U75.17(VCC) U75.30(VCC) U78.10(VCC) ; also on sheet 5 6 7 8 10 11 12 13 14 15 16 17 18 19 20 21 23 24 25 26 27 29 30 39 40
VDD_1V0: C36.1 C39.1 C41.1 C51.1 C238.1 C253.1 C259.1 C263.1 C274.1 U15.6(VDD1P0) U15.24(VDD1P0) U15.31(VDD1P0) U15.42(VDD1P0) ; also on sheet 16
VDD_2V5: C38.1 C43.1 C249.1 C258.1 C261.1 U15.3(VDDA2P5) U15.9(VDDA2P5) ; also on sheet 16 39 40
VDD_CORE: C315.1 C318.1 C323.1 C324.1 C325.1 C329.1 C332.1 C334.1 C335.1 C336.1 C339.1 C345.1 C352.1 C354.1 C482.1 C483.1 C484.1 R298.1 TP55.1(TP) ; also on sheet 4 14 15 25
VDD_DDR4: C288.1 C290.1 C294.1 C302.1 C303.1 C307.1 C308.1 C310.1 C311.1 C314.1 C317.1 ; also on sheet 4 14 16 22
VDD_MMC1: C119.1 C382.1 ; also on sheet 4 24
VDDA_1V8: C79.1 C338.1 C342.1 C346.1 C370.1 ; also on sheet 4 14
VDDR_CORE: C86.2 C87.1 C330.1 C475.1 R307.1 TP61.1(TP) ; also on sheet 4 25
VDDSHV_SD_IO: C372.1 C381.1 ; also on sheet 4 24
CPSW_EARTH: C287.1 J14.SH1 J14.SH2 R299.1
CPSW_ETH1_D0M: J14.10 U15.2(TD_M_A)
CPSW_ETH1_D0P: J14.11 U15.1(TD_P_A)
CPSW_ETH1_D1M: J14.5 U15.5(TD_M_B)
CPSW_ETH1_D1P: J14.4 U15.4(TD_P_B)
CPSW_ETH1_D2M: J14.2 U15.8(TD_M_C)
CPSW_ETH1_D2P: J14.3 U15.7(TD_P_C)
CPSW_ETH1_D3M: J14.9 U15.11(TD_M_D)
CPSW_ETH1_D3P: J14.8 U15.10(TD_P_D)
CPSW_ETH1_GPIO_0: R41.2 R230.2 R251.1 U15.39(GPIO_0)
CPSW_ETH1_GPIO_1: R35.2 R36.1 U15.40(GPIO_1)
CPSW_ETH1_LED0: TP9.1(TP) U15.47(LED_0)
CPSW_ETH1_LED1: J14.13 Q13.3(D)
CPSW_ETH1_LED2: J14.16 Q12.3(D) R234.1
CPSW_ETH1_LED3: J14.15 Q3.3(D) R37.1
CPSW_ETH1_LED_1000: R30.2 R31.1 R32.2 U15.46(LED_1)
CPSW_ETH1_LED_ACT: R33.2 R34.1 R286.1 U15.45(LED_2)
CPSW_FET2_ENn: R335.1 U78.9(~{EN})
CPSW_FET2_SEL: R337.1 U78.1(SEL) ; also on sheet 13
CPSW_FET_EN: R278.2 U75.8(EN)
CPSW_FET_SEL: R292.1 U75.9(SEL1) U75.10(SEL2) ; also on sheet 13
CPSW_RGMII1_ETH1_CLK: U15.15(XI) ; also on sheet 11
CPSW_RGMII1_ETH1_CLK_OUT: TP16.1(TP) U15.18(CLK_OUT)
CPSW_RGMII1_ETH1_RBIAS: R70.1 U15.12(RBIAS)
CPSW_RGMII1_MDC: R81.2 U15.16(MDC) U78.8(B0) ; also on sheet 39
CPSW_RGMII1_MDIO: R79.1 U15.17(MDIO) U78.2(A0) ; also on sheet 39
CPSW_RGMII1_RD0: R54.1 R56.2 U15.33(RX_D0) U75.41(B0)
CPSW_RGMII1_RD1: U15.34(RX_D1) U75.39(B1)
CPSW_RGMII1_RD2: R51.2 R52.1 U15.35(RX_D2) U75.38(B2)
CPSW_RGMII1_RD3: U15.36(RX_D3) U75.36(B3)
CPSW_RGMII1_RESETn: R240.1 U15.43(RESET_N) U69.4(Y)
CPSW_RGMII1_RX_CTL: R39.1 R249.1 U15.38(RX_DV/RX_CTRL) U75.34(B4)
CPSW_RGMII1_RXC: U15.32(RX_CLK) U75.32(B5)
CPSW_RGMII1_TD0: U15.28(TX_D0) ; also on sheet 18
CPSW_RGMII1_TD1: U15.27(TX_D1) ; also on sheet 18
CPSW_RGMII1_TD2: U15.26(TX_D2) ; also on sheet 18
CPSW_RGMII1_TD3: U15.25(TX_D3) ; also on sheet 18
CPSW_RGMII1_TX_CTL: U15.37(TX_EN/TX_CTRL) ; also on sheet 18
CPSW_RGMII1_TXC: U15.29(GTX_CLK) ; also on sheet 18
CPSW_RGMII_INTn: R42.1 R250.2 U15.44(INT/PWDN)
GPIO_CPSW1_RST: R241.1 R242.1 U69.1(A) ; also on sheet 13
HSE_PRG0_PRU0_GPO9: U75.33(C4) ; also on sheet 18
HSE_PRG0_PRU0_GPO10: U75.31(C5) ; also on sheet 18
HSE_PRG0_PRU1_GPO7: U75.42(C0) ; also on sheet 18
HSE_PRG0_PRU1_GPO9: U75.40(C1) ; also on sheet 18
HSE_PRG0_PRU1_GPO10: U75.37(C2) ; also on sheet 18
HSE_PRG0_PRU1_GPO17: U75.35(C3) ; also on sheet 18
HSE_PRG0_PRU1_GPO18: U78.3(A1) ; also on sheet 18
HSE_PRG0_PRU1_GPO19: U78.7(B1) ; also on sheet 18
PORz_OUT: U69.2(B) ; also on sheet 12 24 29 39 40
PRG0_PRU0_GPO9/CPSW_RGMII1_RX_CTL: U75.6(A4) ; also on sheet 18
PRG0_PRU0_GPO10/CPSW_RGMII1_RXC: U75.7(A5) ; also on sheet 18
PRG0_PRU1_GPO7/CPSW_RGMII1_RD0: U75.2(A0) ; also on sheet 18
PRG0_PRU1_GPO9/CPSW_RGMII1_RD1: U75.3(A1) ; also on sheet 18
PRG0_PRU1_GPO10/CPSW_RGMII1_RD2: U75.4(A2) ; also on sheet 18
PRG0_PRU1_GPO17/CPSW_RGMII1_RD3: U75.5(A3) ; also on sheet 18
PRG0_PRU1_GPO18/CPSW_RGMII1_MDIO: U78.4(A) ; also on sheet 18
PRG0_PRU1_GPO19/CPSW_RGMII1_MDC: U78.6(B) ; also on sheet 18
PRG1_RGMII_INTn: R250.1 ; also on sheet 12 39 40
SOC_DVDD1V8: C97.1 C98.2 C359.1 C371.1 C379.1 C383.1 ; also on sheet 4 14
SoC_DVDD3V3: C304.1 C309.1 C312.1 C319.1 C321.1 C326.1 C328.1 C331.1 C333.1 C337.1 C343.1 C351.1 C360.1 C361.1 C364.1 C366.2 C374.1 C376.1 C378.1 ; also on sheet 4 14
N5126260: TP11.1(TP) U15.13(VDDA1P8) U15.48(VDDA1P8)
N18116794: Q13.1(G) R286.2
N18116818: Q12.1(G) R230.1
N18116875: Q3.1(G) R30.1
N26314477: C278.1 C279.1 C285.1 R298.2
N26314562: C291.1 C292.1 C296.1 R307.2
N27215594: J14.14 R76.2
N27215846: C231.2 J14.12
N27215858: C240.2 J14.6
N27215870: C273.2 J14.1
N27215882: C282.2 J14.7

Not connected (* = marked no-connect by the designer): U15 14(XO)* 20(JTAG_CLK)* 21(JTAG_TDO)* 22(JTAG_TMS)* 23(JTAG_TDI)*; U75 11(A6)* 12(A7)* 13(A8)* 14(A9)* 15(A10)* 16(A11)* 18(C11)* 19(B11)* 20(C10)* 21(B10)* 22(C9)* 23(B9)* 24(C8)* 25(B8)* 26(C7)* 27(B7)* 28(C6)* 29(B6)*

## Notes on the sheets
sheet 1
- BLOCK DIAGRAM_XDS110
sheet 2
- Decaps
- CPSW RGMII 1 -  PHY
- RJ45 with Integrated Mangnetics
- STRAPPING RESISTORS
- CPSW ETH1 RESET
- CPSW_ETHERNET PHY- 1 SPEED & ACTIVITY  LED 's DRIVERS
- PHY ADDRESS = 00000
- Auto-negotiation Enabled
- 10/100/1000 advertised, Auto-MDI-X
- Tx & Rx Clock Skew = 2.0ns
- CPSW RGMII 1 ETHERNET PHY SIGNALS & HSE CON SIGNALS
- MDC/MDIO FET SWITCH
- Off Page Connections
- From
  Processor
- From Processor
- TMUX154EDGSR Truth Table
- To ICSSG1 ETH FET SW
- SEL
- EN#
- FUNCTION
- From IO Expander
- X
- H
- DISCONNECT
- From Clock Buffer
- L
- L
- A=A0 , B=B0
- TS3DDR3812RUAR Truth Table
- H
- L
- A=A1 , B=B1
- To HSE Connector
- EN
- SEL1
- SEL2
- FUNCTION
- To HSE Connector
- L
- X
- X
- A0 to A11, B0 to B11, and C0 to C11 are Hi-Z
- From Processor
- H
- L
- L
- A0 to A5 = B0 to B5 and A6 to A11 = B6 to B11
- H
- L
- H
- A0 to A5 = B0 to B5 and A6 to A11 = C6 to C11
- H
- H
- L
- A0 to A5 = C0 to C5 and A6 to A11 = B6 to B11
- H
- H
- H
- A0 to A5 = C0 to C5 and A6 to A11 = C6 to C11
sheet 3
- SoC POWER Decaps
- Place one 0.1uF cap near each Pin
- To place after current sense
  resitor on VDD_CORE plane
- Place one 0.1uF cap near each Pin
- VDD ARRAY CORE
- VDDA_3P3_SDIO
- Place one 0.1uF cap near each Pin
- Place one 0.1uF cap near each Pin
- Core & Array Core Supply Kelvin Sensing
